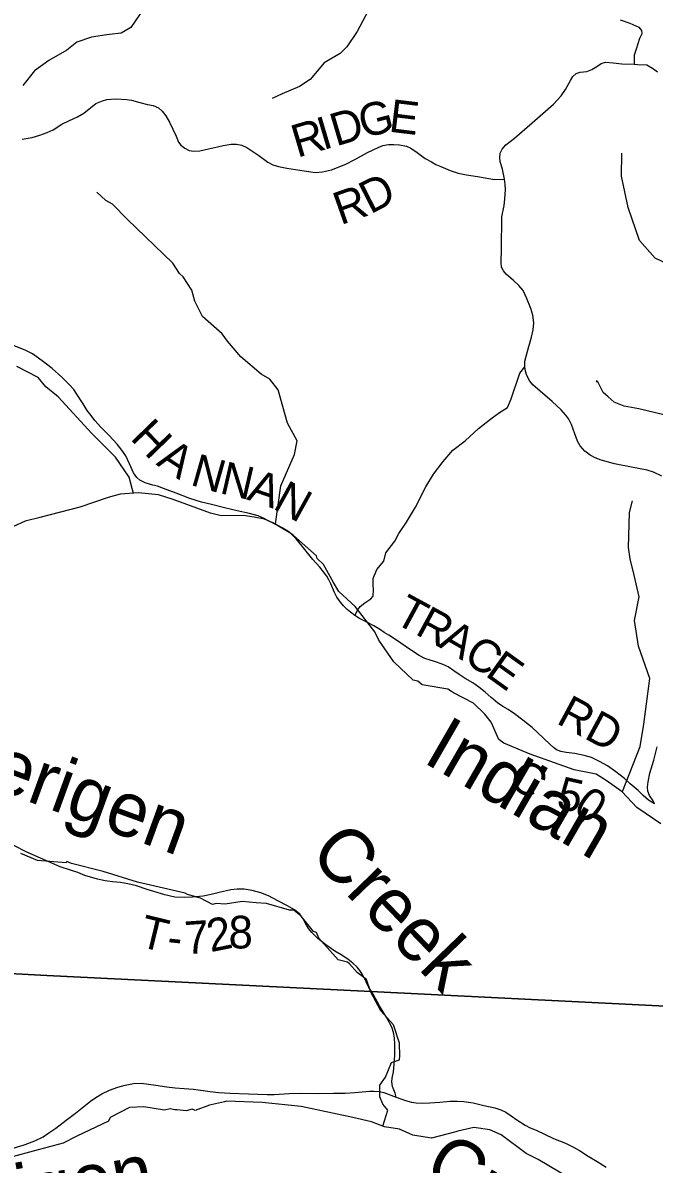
# Model space of a CAD drawing. Extents: x -1.8 to 75.7, y -2 to 25.
# Drawn here: x 44.794 to 45.89, y 18.595 to 20.577 of the extents above; entities that cross this region are included whole.
import ezdxf

# ---------------------------------------------------------------- set-up
doc = ezdxf.new("R2010")
doc.units = 0
for name, color, linetype in [('GM_X_County_Road', 7, 'Continuous'), ('GM_X_County_Road_Text', 7, 'Continuous'), ('GM_X_Minor_River', 7, 'Continuous'), ('GM_X_Minor_River_Text', 7, 'Continuous'), ('GM_X_State_Route', 7, 'Continuous'), ('GM_X_Township', 7, 'Continuous'), ('GM_X_Township_Road', 7, 'Continuous'), ('GM_X_Township_Road_Text', 7, 'Continuous'), ('GM_X_Township_ROW', 7, 'Continuous')]:
    doc.layers.add(name, color=color, linetype=linetype)

msp = doc.modelspace()

# ---------------------------------------------------------------- linework, layer by layer
at = {"layer": 'GM_X_County_Road'}
for points in [[(45.9035, 19.7901), (45.889, 19.7969), (45.8782, 19.8001), (45.8511, 19.8057), (45.8215, 19.8111), (45.7982, 19.8177), (45.7878, 19.8215), (45.7792, 19.8265), (45.77, 19.8333), (45.7621, 19.8428), (45.7571, 19.8509), (45.7528, 19.8633), (45.7469, 19.8794), (45.7422, 19.8888), (45.7368, 19.8961), (45.7289, 19.9051), (45.7131, 19.9193), (45.6923, 19.9374), (45.6796, 19.9487), (45.6742, 19.955), (45.6692, 19.965), (45.6667, 19.9722), (45.6656, 19.9797), (45.6656, 19.9855), (45.6658, 19.9894), (45.669, 20.0022), (45.6726, 20.0151), (45.6774, 20.0314), (45.6803, 20.044), (45.6814, 20.056), (45.6794, 20.0693), (45.676, 20.0811), (45.6686, 20.0996), (45.6627, 20.1125), (45.6555, 20.1211), (45.646, 20.1299), (45.6335, 20.1407), (45.6288, 20.1466), (45.6252, 20.1529), (45.6245, 20.161), (45.6254, 20.1848), (45.6261, 20.2401), (45.6297, 20.2598), (45.6308, 20.2711), (45.6322, 20.288), (45.6317, 20.2964), (45.6307, 20.3059), (45.6268, 20.3229), (45.6232, 20.336), (45.6223, 20.3434), (45.6232, 20.3511), (45.6262, 20.3577), (45.6328, 20.3654), (45.648, 20.3772), (45.6783, 20.4036), (45.7154, 20.4363), (45.7286, 20.4504), (45.7365, 20.4617), (45.7449, 20.4771), (45.7493, 20.4839), (45.7551, 20.4894), (45.7617, 20.4916), (45.7735, 20.4926), (45.7824, 20.4961), (45.7908, 20.5016), (45.7983, 20.5066), (45.8057, 20.5091), (45.8194, 20.5076), (45.8343, 20.5063), (45.8554, 20.5054), (45.8614, 20.5048), (45.8774, 20.5046), (45.8872, 20.4988), (45.896, 20.4924)], [(45.8908, 19.2209), (45.8807, 19.2274), (45.8712, 19.2351), (45.8624, 19.2437), (45.8488, 19.2554), (45.8387, 19.2647), (45.8237, 19.2762), (45.8095, 19.2866), (45.7953, 19.2943), (45.7813, 19.3011), (45.7686, 19.3047), (45.7528, 19.3081), (45.7375, 19.3101), (45.7284, 19.3119), (45.721, 19.3148), (45.7155, 19.3187), (45.7099, 19.3236), (45.6984, 19.3347), (45.688, 19.3447), (45.6787, 19.3532), (45.6625, 19.3661), (45.6478, 19.3772), (45.6369, 19.3844), (45.6274, 19.3898), (45.6184, 19.3962), (45.6076, 19.4052), (45.5967, 19.4147), (45.5859, 19.4237), (45.5757, 19.4307), (45.5622, 19.4386), (45.552, 19.4452), (45.5427, 19.4517), (45.5328, 19.4585), (45.5224, 19.4633), (45.5091, 19.4678), (45.4919, 19.4734), (45.4822, 19.4784), (45.4725, 19.4845), (45.4578, 19.4949), (45.4431, 19.5048), (45.4298, 19.5136), (45.4216, 19.5186), (45.4149, 19.5229), (45.4036, 19.5301), (45.3923, 19.536), (45.3787, 19.5428), (45.3706, 19.5477), (45.3631, 19.5534), (45.3573, 19.5581), (45.3509, 19.5647), (45.3455, 19.5708), (45.3392, 19.5796), (45.3351, 19.5877), (45.3288, 19.6029), (45.3256, 19.6099), (45.322, 19.6162), (45.3164, 19.6236), (45.3098, 19.632), (45.2979, 19.6453), (45.2881, 19.6566), (45.2793, 19.6681), (45.2689, 19.6812), (45.2606, 19.6891), (45.254, 19.6943), (45.2443, 19.7004), (45.2328, 19.7063), (45.2215, 19.712), (45.2129, 19.7165), (45.2025, 19.7208), (45.1876, 19.7251), (45.1664, 19.7298), (45.1463, 19.7343), (45.1214, 19.7404), (45.1043, 19.7449), (45.0842, 19.751), (45.06, 19.7601), (45.0385, 19.7687), (45.0281, 19.7725), (45.0196, 19.7745), (45.0067, 19.7784), (44.9974, 19.7827), (44.992, 19.7876), (44.9861, 19.7958), (44.9791, 19.8111), (44.9726, 19.8254), (44.9662, 19.8351), (44.9577, 19.8457), (44.9439, 19.8606), (44.9299, 19.8746), (44.9193, 19.8864), (44.9125, 19.8952), (44.9059, 19.904), (44.8989, 19.9155), (44.8869, 19.9338), (44.8824, 19.9403), (44.8752, 19.9487), (44.8616, 19.9618), (44.8452, 19.9769), (44.8278, 19.9905), (44.8106, 20.0022), (44.7979, 20.009), (44.7792, 20.0165)], [(45.8908, 19.2209), (45.8885, 19.2259), (45.8821, 19.235), (45.8794, 19.2427), (45.8788, 19.2499), (45.8797, 19.2592), (45.883, 19.2742), (45.8896, 19.2966), (45.8953, 19.3199)]]:
    msp.add_lwpolyline(points, dxfattribs=at)
at = {"layer": 'GM_X_Minor_River'}
for points in [[(45.1877, 20.8556), (45.1828, 20.8531), (45.1684, 20.8289), (45.1644, 20.7952), (45.151, 20.7789), (45.1282, 20.7728), (45.1006, 20.7486), (45.0859, 20.7259), (45.0744, 20.7183), (45.0533, 20.7083), (45.0266, 20.6515), (45.0227, 20.6356), (45.0182, 20.6229), (44.9814, 20.5693), (44.9648, 20.5592), (44.9447, 20.5568), (44.9398, 20.5562), (44.9132, 20.5525), (44.8876, 20.5435), (44.8706, 20.5296), (44.839, 20.5116), (44.814, 20.4942), (44.7943, 20.4682)], [(45.4087, 20.6268), (45.3747, 20.5625), (45.3569, 20.5357), (45.3452, 20.524), (45.3175, 20.5078), (45.2928, 20.4789), (45.2743, 20.4666), (45.2444, 20.4539), (45.2268, 20.4457)], [(46.0414, 19.839), (46.0278, 19.8743), (46.0086, 19.9099), (46.0089, 19.9301), (46.0173, 19.9723), (46.0164, 19.9977), (45.9943, 20.0717), (45.9767, 20.105), (45.9457, 20.1394), (45.903, 20.1635), (45.8924, 20.1687), (45.8649, 20.1993), (45.8452, 20.2566), (45.8334, 20.3112), (45.834, 20.3507)], [(45.2327, 19.7071), (45.2419, 19.7732), (45.2658, 19.8276), (45.2703, 19.851), (45.2539, 19.8822), (45.2375, 19.9401), (45.2229, 19.9584), (45.2081, 19.9673), (45.1727, 19.9969), (45.1497, 20.0242), (45.1399, 20.0374), (45.106, 20.067), (45.0928, 20.094), (45.0873, 20.1128), (45.0725, 20.136), (45.0663, 20.1419), (45.0544, 20.1598), (44.9754, 20.2363), (44.9497, 20.2622), (44.9382, 20.2687), (44.9224, 20.2832)], [(44.9863, 19.7596), (44.9788, 19.788), (44.955, 19.8229), (44.9139, 19.8641), (44.8553, 19.9279), (44.8339, 19.9449), (44.8204, 19.9613), (44.7836, 19.9803)], [(46.0134, 19.8623), (45.988, 19.8697), (45.9834, 19.8701), (45.9607, 19.8807), (45.9195, 19.8935), (45.8636, 19.9071), (45.8382, 19.9116), (45.8212, 19.9184), (45.8106, 19.9275), (45.8019, 19.9354), (45.7928, 19.9536), (45.7898, 19.9552), (45.7906, 19.9529)], [(45.8072, 19.2615), (45.7894, 19.2721), (45.7516, 19.28), (45.6748, 19.3068), (45.6294, 19.326), (45.6207, 19.3325), (45.6075, 19.3628), (45.5961, 19.3765), (45.5768, 19.3958), (45.542, 19.4136), (45.5382, 19.4159), (45.5322, 19.4197), (45.4876, 19.4276), (45.48, 19.4336), (45.4721, 19.4355), (45.4384, 19.4677), (45.4123, 19.5049), (45.4054, 19.5193), (45.371, 19.5634), (45.343, 19.5895), (45.3335, 19.6051), (45.3161, 19.6362), (45.3051, 19.6468), (45.304, 19.6518), (45.2643, 19.6866), (45.2597, 19.6901), (45.2283, 19.709), (45.2136, 19.7154), (45.1958, 19.7188), (45.1769, 19.7218), (45.1387, 19.7209), (45.1198, 19.7258), (45.0548, 19.7492), (45.0294, 19.7575), (44.9947, 19.7609), (44.9629, 19.7589), (44.9421, 19.7531), (44.893, 19.7363), (44.8237, 19.7181)], [(45.8354, 19.2424), (45.8658, 19.3201), (45.8726, 19.3589), (45.883, 19.4387), (45.8631, 19.4944), (45.8565, 19.5391), (45.8646, 19.5806), (45.8559, 19.6181), (45.8488, 19.6464), (45.8456, 19.6659), (45.8474, 19.7266), (45.8526, 19.7473)], [(44.824, 19.7182), (44.8004, 19.7125), (44.7978, 19.7117), (44.7777, 19.7026), (44.7483, 19.6979), (44.7309, 19.6975), (44.6783, 19.7076), (44.6424, 19.719), (44.6031, 19.7257), (44.5815, 19.7272), (44.5245, 19.7225), (44.4708, 19.7117)], [(45.9017, 19.186), (45.8605, 19.2145), (45.8348, 19.2418), (45.8072, 19.2615)], [(45.4192, 18.661), (45.4278, 18.6889), (45.4191, 18.6991), (45.4138, 18.712), (45.4142, 18.7322), (45.424, 18.7462), (45.4342, 18.7714), (45.4481, 18.7763), (45.4485, 18.7828), (45.4481, 18.8048), (45.4375, 18.8367), (45.4155, 18.8614), (45.3981, 18.8937), (45.3909, 18.9157), (45.3747, 18.9278), (45.3614, 18.9426), (45.3576, 18.9456), (45.3417, 18.9498), (45.3081, 18.9873), (45.3039, 18.9972), (45.2986, 18.9991), (45.2774, 19.0256), (45.2645, 19.0359), (45.257, 19.0362), (45.2173, 19.0475), (45.1995, 19.0486), (45.1749, 19.0509), (45.1455, 19.0466), (45.13, 19.0477), (45.1232, 19.0462), (45.1027, 19.0571), (45.0797, 19.0635), (45.0759, 19.0654), (44.9931, 19.085), (44.9337, 19.1031), (44.8785, 19.1174), (44.8702, 19.1208), (44.8694, 19.1185), (44.8192, 19.1226), (44.7904, 19.1347)], [(45.1478, 18.7045), (45.1443, 18.703), (45.1182, 18.6976), (45.0933, 18.688), (45.0883, 18.6903), (45.0774, 18.6876), (45.0619, 18.6891), (45.0581, 18.6891), (45.0498, 18.691), (45.04, 18.689), (45.004, 18.6947), (44.9791, 18.6935), (44.9459, 18.6759), (44.9425, 18.6698), (44.8877, 18.6438), (44.8642, 18.6316), (44.8204, 18.6197), (44.7694, 18.6059), (44.7358, 18.5906)], [(45.7629, 18.5593), (45.6891, 18.6032), (45.6683, 18.6134), (45.6244, 18.646), (45.6051, 18.6543), (45.5772, 18.6588), (45.5496, 18.6523), (45.5458, 18.6508), (45.5035, 18.64), (45.4713, 18.6453), (45.4483, 18.6555), (45.4218, 18.66), (45.3995, 18.6687), (45.367, 18.6758), (45.2774, 18.695), (45.2097, 18.702), (45.1478, 18.7045)]]:
    msp.add_lwpolyline(points, dxfattribs=at)
at = {"layer": 'GM_X_State_Route'}
for points in [[(44.798, 18.6293), (44.8149, 18.6355), (44.8291, 18.6426), (44.8393, 18.6491), (44.8514, 18.6576), (44.8695, 18.6714), (44.8853, 18.6835), (44.9114, 18.7046), (44.9209, 18.7109), (44.931, 18.7168), (44.9446, 18.7233), (44.959, 18.7287), (44.9718, 18.7324), (44.9864, 18.7352), (44.9997, 18.7356), (45.0247, 18.7322), (45.0441, 18.7291), (45.0587, 18.7275), (45.0739, 18.7263), (45.0903, 18.7249), (45.1193, 18.721), (45.1345, 18.7194), (45.1541, 18.7184), (45.1858, 18.717), (45.2184, 18.7158), (45.2303, 18.7158), (45.2565, 18.7174), (45.2776, 18.718), (45.3057, 18.7178), (45.3335, 18.7182), (45.3535, 18.7185), (45.3706, 18.7196), (45.3961, 18.7216), (45.4036, 18.722), (45.4135, 18.7212), (45.4212, 18.7194), (45.4423, 18.7111), (45.4583, 18.7054), (45.4692, 18.7028), (45.4771, 18.7016), (45.4873, 18.701), (45.5009, 18.7014), (45.5179, 18.7028), (45.5361, 18.7045), (45.5484, 18.7045), (45.56, 18.7038), (45.576, 18.7015), (45.5946, 18.6969), (45.6138, 18.6926), (45.624, 18.6891), (45.633, 18.6851), (45.6423, 18.6787), (45.652, 18.672), (45.6666, 18.6627), (45.6753, 18.6582), (45.6852, 18.6538), (45.7154, 18.6397), (45.7363, 18.6312), (45.7502, 18.6244), (45.761, 18.6185), (45.7758, 18.609), (45.7914, 18.5993), (45.8068, 18.5898)], [(44.4927, 18.6032), (44.5163, 18.6104), (44.5304, 18.6138), (44.5465, 18.6167), (44.56, 18.6185), (44.5698, 18.6191), (44.6243, 18.6175), (44.6543, 18.6163), (44.6688, 18.6159), (44.6972, 18.6149), (44.724, 18.6148), (44.7381, 18.6157), (44.7507, 18.6171), (44.7631, 18.6191), (44.7762, 18.6223), (44.7845, 18.6248), (44.7945, 18.628), (44.798, 18.6293)]]:
    msp.add_lwpolyline(points, dxfattribs=at)
at = {"layer": 'GM_X_Township'}
for points in [[(43.8002, 18.978), (44.8356, 18.9224), (45.3865, 18.8952), (46.1197, 18.859), (46.3714, 18.8466), (46.9192, 18.8195), (47.1815, 18.806), (47.9522, 18.7663), (48.0201, 19.5982), (48.0214, 19.6198), (48.0228, 19.6698), (48.0235, 19.6926), (48.0261, 19.7186), (48.0301, 19.7636), (48.0891, 20.7799), (48.1186, 21.2763), (48.1494, 21.7937), (48.1876, 22.5121)], [(47.7632, 15.7121), (47.7893, 16.1371), (47.8138, 16.5363), (47.826, 16.7363), (47.8708, 17.4759), (47.8899, 17.791), (47.9266, 18.366), (47.9522, 18.7663), (47.1815, 18.806), (46.9192, 18.8195), (46.3714, 18.8466), (46.1197, 18.859), (45.3865, 18.8952), (44.8356, 18.9224), (43.8002, 18.978)]]:
    msp.add_lwpolyline(points, dxfattribs=at)
at = {"layer": 'GM_X_Township_Road'}
for points in [[(44.7929, 20.3753), (44.81, 20.3783), (44.8237, 20.3822), (44.8363, 20.3867), (44.8466, 20.3916), (44.8618, 20.401), (44.8748, 20.4074), (44.8891, 20.4142), (44.9, 20.4206), (44.921, 20.4373), (44.9325, 20.4418), (44.9396, 20.4439), (44.9554, 20.4452), (44.9746, 20.444), (44.9828, 20.4431), (44.9971, 20.4392), (45.0106, 20.4356), (45.0204, 20.4335), (45.0294, 20.4299), (45.0362, 20.4236), (45.0426, 20.4155), (45.0488, 20.4046), (45.0546, 20.3926), (45.06, 20.3807), (45.0642, 20.3702), (45.0685, 20.3651), (45.0754, 20.3595), (45.0831, 20.3556), (45.0908, 20.3546), (45.1012, 20.3552), (45.1162, 20.3586), (45.1318, 20.3619), (45.1418, 20.3644), (45.1557, 20.3663), (45.1649, 20.3668), (45.1741, 20.3651), (45.1831, 20.361), (45.2036, 20.3471), (45.2197, 20.3353), (45.2284, 20.3306), (45.2378, 20.3277), (45.2524, 20.3249), (45.2823, 20.32), (45.3022, 20.3176), (45.3142, 20.3185), (45.33, 20.3217), (45.3548, 20.3317), (45.3704, 20.34), (45.3926, 20.3522), (45.411, 20.3608), (45.4192, 20.364), (45.4288, 20.3659), (45.4384, 20.3661), (45.4484, 20.3653), (45.4602, 20.3631), (45.4677, 20.3595), (45.479, 20.3522), (45.4927, 20.3418), (45.5036, 20.3356), (45.5111, 20.3315), (45.5201, 20.3277), (45.5363, 20.3208), (45.5498, 20.3161), (45.5645, 20.3133), (45.5836, 20.3103), (45.6129, 20.3054), (45.6307, 20.3059)], [(45.3972, 18.8985), (45.3951, 18.902), (45.3902, 18.9115), (45.3837, 18.9241), (45.3793, 18.9314), (45.3748, 18.9372), (45.3673, 18.9441), (45.3586, 18.9512), (45.3471, 18.9583), (45.3357, 18.965), (45.3203, 18.9757), (45.3065, 18.9869), (45.2956, 18.9972), (45.2907, 19.0035), (45.2865, 19.0102), (45.281, 19.0211), (45.2749, 19.0294), (45.2658, 19.0367), (45.2538, 19.0434), (45.237, 19.0521), (45.2208, 19.061), (45.2074, 19.0663), (45.192, 19.07), (45.1785, 19.0724), (45.1661, 19.0724), (45.1552, 19.0712), (45.1347, 19.0669), (45.1213, 19.0633), (45.1071, 19.0606), (45.0885, 19.0586), (45.0741, 19.0582), (45.0577, 19.0586), (45.0407, 19.0625), (45.0216, 19.0687), (45.0099, 19.0722), (44.9914, 19.0781), (44.9762, 19.0821), (44.9635, 19.0841), (44.9497, 19.0852), (44.9371, 19.0872), (44.9234, 19.0902), (44.9019, 19.0965), (44.8897, 19.1016), (44.8769, 19.1058), (44.8591, 19.1113), (44.8338, 19.1224), (44.8012, 19.1368), (44.7783, 19.1482)], [(45.4423, 18.7111), (45.4407, 18.7184), (45.436, 18.7301), (45.4348, 18.738), (45.4356, 18.7443), (45.4378, 18.7553), (45.4389, 18.7678), (45.4399, 18.7845), (45.4399, 18.8029), (45.4393, 18.8142), (45.4376, 18.8238), (45.4346, 18.8329), (45.4259, 18.8493), (45.4135, 18.8702), (45.4028, 18.8888), (45.3995, 18.8946), (45.3972, 18.8985)]]:
    msp.add_lwpolyline(points, dxfattribs=at)
at = {"layer": 'GM_X_Township_ROW'}
for points in [[(45.8313, 20.5823), (45.8484, 20.5767), (45.8636, 20.5695), (45.8685, 20.5637), (45.8687, 20.5584), (45.8648, 20.5498), (45.8593, 20.5317), (45.8554, 20.521), (45.8554, 20.5054)], [(45.3706, 19.5477), (45.3757, 19.5577), (45.3801, 19.5638), (45.3877, 19.5701), (45.3984, 19.5766), (45.4026, 19.5817), (45.4028, 19.593), (45.4022, 19.6), (45.4022, 19.6119), (45.4089, 19.6277), (45.4207, 19.6424), (45.4245, 19.6567), (45.4403, 19.6771), (45.4472, 19.6904), (45.4602, 19.7099), (45.476, 19.7358), (45.4937, 19.7715), (45.5071, 19.7936), (45.5238, 19.8153), (45.5408, 19.8348), (45.5622, 19.851), (45.5852, 19.8729), (45.6089, 19.8912), (45.6215, 19.9004), (45.6359, 19.9094), (45.6419, 19.9244), (45.6573, 19.9686), (45.6656, 19.9797)]]:
    msp.add_lwpolyline(points, dxfattribs=at)

# ---------------------------------------------------------------- texts
at = {"layer": 'GM_X_County_Road_Text'}
for s, height, rotation, p in [('H', 0.0568, 314.1525, (44.9789, 19.855)), ('A', 0.0568, 326.6004, (45.0241, 19.8105)), ('N', 0.0568, 344.1566, (45.0831, 19.7751)), ('N', 0.0568, 347.0117, (45.1341, 19.7607)), ('A', 0.0568, 340.8618, (45.1813, 19.7499)), ('N', 0.0568, 330.9905, (45.2262, 19.7346)), ('T', 0.0568, 331.5142, (45.4361, 19.5367)), ('R', 0.0568, 331.4553, (45.4734, 19.5165)), ('A', 0.0568, 329.9809, (45.5141, 19.4944)), ('C', 0.0568, 326.58, (45.5566, 19.4698)), ('E', 0.0568, 324.4262, (45.5951, 19.4444)), ('RD', 0.05682, 331.6659, (45.7185, 19.3617)), ('C', 0.0568, 321.4094, (45.633, 19.2595)), ('5', 0.0568, 347.4153, (45.7185, 19.2135)), ('-', 0.0568, 348.5859, (45.6959, 19.2181)), ('0', 0.0568, 325.0216, (45.7473, 19.2082))]:
    msp.add_text(s, height=height, rotation=rotation, dxfattribs=at).set_placement(p)
at = {"layer": 'GM_X_Minor_River_Text'}
for s, height, rotation, p in [('Indian', 0.0947, 330.0018, (45.4863, 19.2943)), ('Perigen', 0.09469, 340.0029, (44.6524, 19.2796)), ('Creek', 0.0947, 314.0019, (45.2888, 19.1318)), ('Creek', 0.09469, 330.0049, (45.4856, 18.5725)), ('Perigen', 0.0947, 10.0083, (44.5959, 18.4636))]:
    msp.add_text(s, height=height, rotation=rotation, dxfattribs=at).set_placement(p)
at = {"layer": 'GM_X_Township_Road_Text'}
for s, rotation, p in [('G', 14.2872, (45.3852, 20.3765)), ('E', 353.0467, (45.4281, 20.3885)), ('D', 16.4693, (45.3378, 20.3625)), ('R', 16.482, (45.2706, 20.3427)), ('I', 16.4878, (45.3154, 20.3559)), ('D', 27.0523, (45.3973, 20.2443)), ('R', 19.3915, (45.3458, 20.2256)), ('T', 346.3411, (44.9935, 18.9734)), ('7', 3.9594, (45.0769, 18.9594)), ('2', 11.512, (45.1199, 18.9629)), ('8', 359.9349, (45.1512, 18.9696)), ('-', 354.1829, (45.0431, 18.962))]:
    msp.add_text(s, height=0.0568, rotation=rotation, dxfattribs=at).set_placement(p)

doc.saveas('drawing.dxf')
